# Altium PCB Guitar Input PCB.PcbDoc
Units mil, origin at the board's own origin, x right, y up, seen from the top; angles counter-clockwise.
Board outline 1700 x 1000 mil, 2 copper layers (Top Layer, Bottom Layer); 18 components, 10 nets, 47 pads, 16 vias.
Unrouted connection lines stored in the file: 9.
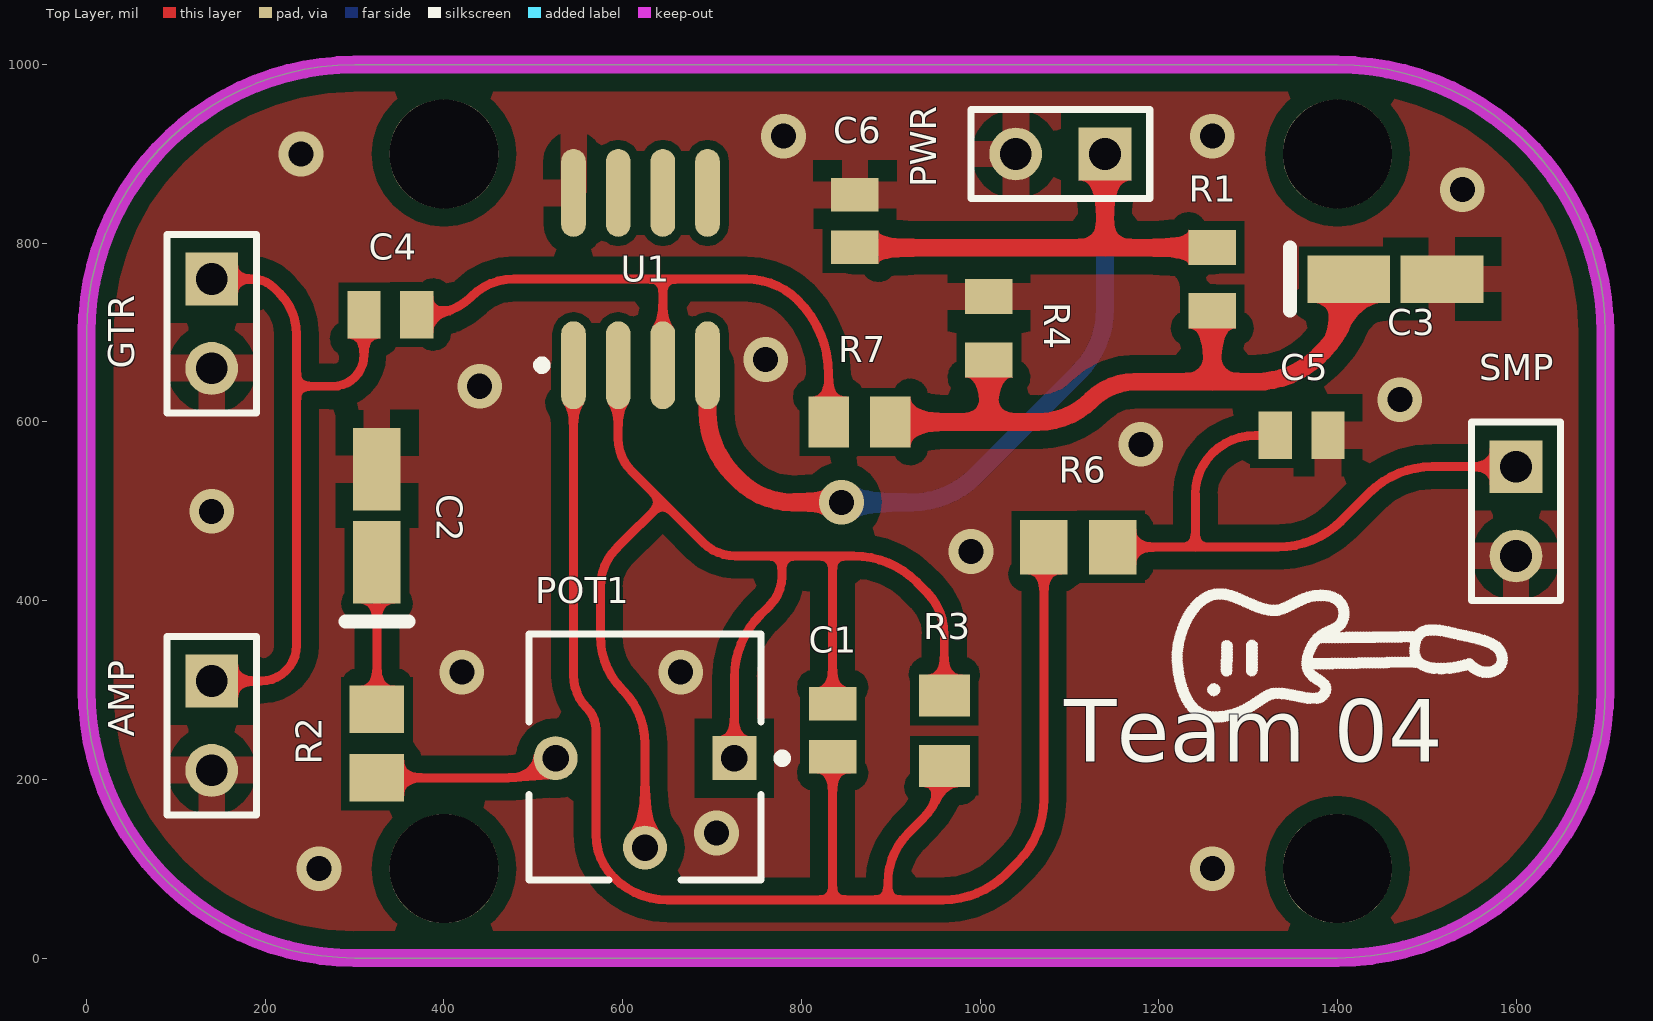
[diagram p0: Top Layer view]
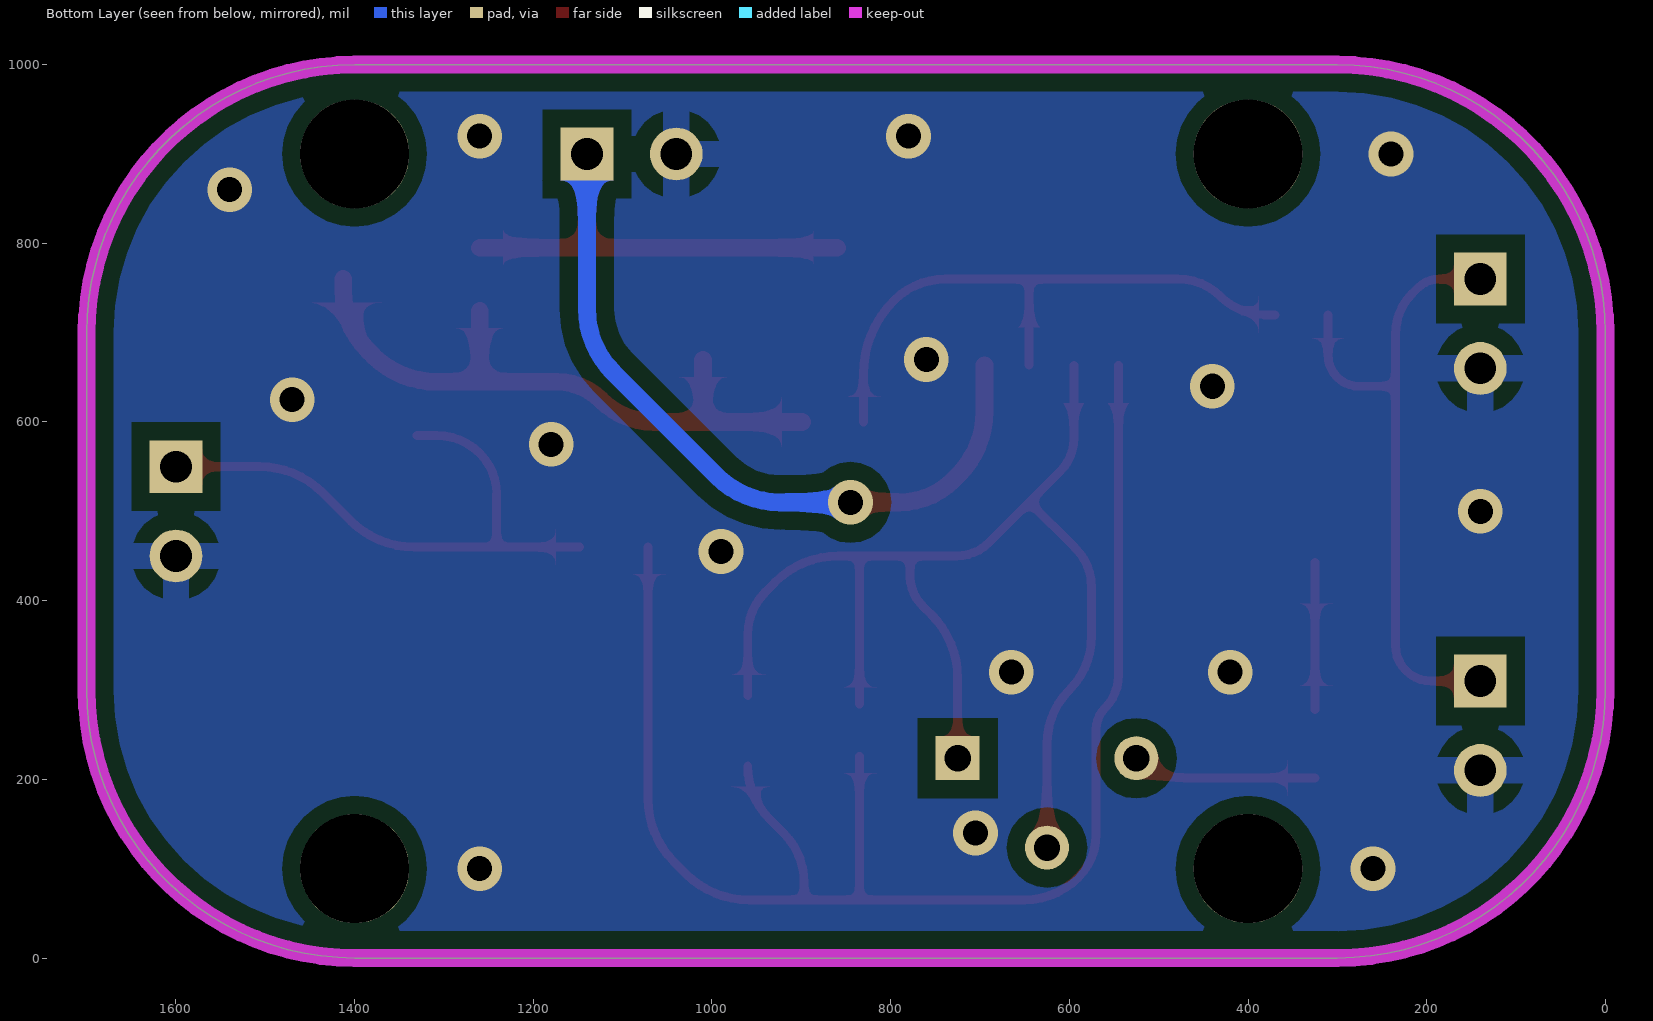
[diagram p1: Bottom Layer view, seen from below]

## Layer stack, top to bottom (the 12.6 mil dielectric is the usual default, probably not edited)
Top Solder: solder mask 0.4, Solder Resist, Dk 3.5
Top Layer: signal copper 1.4
Dielectric 1: dielectric 12.6, FR-4, Dk 4.8
Bottom Layer: signal copper 1.4
Bottom Solder: solder mask 0.4, Solder Resist, Dk 3.5

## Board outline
0,300 0,700 cw(c300,700) 300,1000 1400,1000 cw(c1400,700) 1700,700 1700,300 cw(c1400,300) 1400,0 300,0 cw(c300,300)

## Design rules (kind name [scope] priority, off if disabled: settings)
Clearance [All] p1: gap=10 ignorepadtopadclearanceinfootprint=FALSE except(0: Arc-Hole Track-Hole SMDPad-Hole THPad-Hole Via-Hole Fill-Hole Poly-Hole Region-Hole Text-Hole; 20: Arc-Fill Arc-Poly Arc-Region Track-Fill Track-Poly Track-Region THPad-Fill THPad-Poly THPad-Region Via-Fill Via-Poly Via-Region Fill-Fill Fill-Poly Fill-Region Poly-Poly Poly-Region Region-Region)
PolygonConnect [All] p1: thpad.connectstyle=Relief thpad.reliefconductorwidth=30 thpad.reliefentries=4 thpad.polygonreliefangle="90 Angle" thpad.airgapwidth=20 smdpad.connectstyle=Relief smdpad.reliefconductorwidth=30 smdpad.reliefentries=4 smdpad.polygonreliefangle="90 Angle" smdpad.airgapwidth=20 via.connectstyle=Direct via.reliefconductorwidth=30 via.reliefentries=4 via.polygonreliefangle="90 Angle" via.airgapwidth=20
RoutingVias [All] p1: holewidth=28 width=50 viastyle="Through Hole" minholewidth=28 minwidth=50 maxholewidth=28 maxwidth=50
SolderMaskExpansion [All] p1: expansion=4 istentingtop=FALSE
Width Width_1 [InNet('+2V5') OR InNet('+5V')] p1: maxlimit=30 minlimit=20 preferedwidth=25 minimp=50.000000 maximp=50.000000 favimp=50.000000
Width [All] p2: maxlimit=25 minlimit=10 preferedwidth=20 minimp=50.000000 maximp=50.000000 favimp=50.000000
30 further rules are at their usual default settings.

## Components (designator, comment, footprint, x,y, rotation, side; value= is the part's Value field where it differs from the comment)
AMP "AMPLIFIER_INPUT" HDR1X2 140,310 r270 top
C1 "270pF" FP-C0805C-DN-MFG 835,255 r270 top value="270 pF"
C2 "10uF" KEMT-A-3216-18-2_M 325,495 r90 top
C3 "10uF" KEMT-A-3216-18-2_M 1465,760 r0 top
C4 "100nF" FP-C0805C-DN-MFG 340,720 r0 top value="0.10 μF"
C5 "270pF" FP-C0805C-DN-MFG 1360,585 r180 top value="270 pF"
C6 "100 nF" FP-C0805C-DN-MFG 860,825 r90 top value="0.10 μF"
GTR "GUITAR_OUTPUT" HDR1X2 140,760 r270 top
POT1 "100K" BOUR-3362P 625,225 r180 top
PWR "POWER" HDR1X2 1140,900 r180 top
R1 "10K" RESC2013X60X35NL10T20 1260,760 r90 top
R2 "470" RESC2013X70X40ML20T20 325,240 r270 top
R3 "100K" RESC2013X60X35ML10T20 960,254.37 r270 top
R4 "10K" RESC2013X60X35NL10T20 1010,705 r270 top
R6 "470" RESC2013X70X40ML20T20 1110,460 r0 top
R7 "1M" RESC2013X70X40NL20T20 865,600 r180 top
SMP "SAMPLED_SIGNAL" HDR1X2 1600,550 r270 top
U1 "MCP6002" SOIC-SN8_M 620,760 r90 top

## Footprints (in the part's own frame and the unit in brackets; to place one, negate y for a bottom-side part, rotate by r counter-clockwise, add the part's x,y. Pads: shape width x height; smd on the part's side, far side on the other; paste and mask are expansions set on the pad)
BOUR-3362P [mm] "THD, 3-Leads, Body 6.6x6.99mm, Pitch 2.54mm"
  rect 1.25x1.25 hole 0.75: 1(-2.54,0.035)
  round 1.25 hole 0.75: 2(0,2.575) 3(2.54,0.035)
  silkscreen extent -4.03,-3.49 3.3,3.5, body extent -3.3,-3.49 3.3,3.49, height 4.95
FP-C0805C-DN-MFG [mm]
  rect 0.95x1.35 smd paste+0 mask+0: 1(-0.75,0) 2(0.75,0)
  body extent -1.4,-0.85 1.4,0.85, height 0.25
HDR1X2 [mm] "Connector; Header; 2 Position"
  rect 1.5x1.5 hole 0.9: 1(0,0)
  round 1.5 hole 0.9: 2(2.54,0)
  silkscreen extent -1.27,-1.27 3.81,1.27
KEMT-A-3216-18-2_M [mm] "Molded TAN Capacitor, 2-Leads, Body 3.4x1.8mm, IPC Low Density"
  rect 2.35x1.35 smd: 1(-1.325,0) 2(1.325,0)
  silkscreen extent -3,-0.9 -3,0.9, body extent -1.7,-0.9 1.7,0.9, height 1.8
RESC2013X60X35ML10T20 [mm] "Chip Resistor, 2-Leads, Body 2.1x1.35mm, IPC Low Density"
  rect 1.2x1.45 smd: 1(-1,0) 2(1,0)
  body extent -1.05,-0.68 1.05,0.67, height 0.6
RESC2013X60X35NL10T20 [mm] "Chip Resistor, 2-Leads, Body 2.1x1.35mm, IPC Medium Density"
  rect 1x1.35 smd: 1(-0.9,0) 2(0.9,0)
  body extent -1.05,-0.68 1.05,0.67, height 0.6
RESC2013X70X40ML20T20 [mm] "Chip Resistor, 2-Leads, Body 2.00x1.25mm, IPC Low Density"
  rect 1.35x1.55 smd: 1(-0.975,0) 2(0.975,0)
  body extent -1.1,-0.72 1.1,0.72, height 0.7
RESC2013X70X40NL20T20 [mm] "Chip Resistor, 2-Leads, Body 2.2x1.35mm, IPC Medium Density"
  rect 1.15x1.45 smd: 1(-0.875,0) 2(0.875,0)
  body extent -1.1,-0.72 1.1,0.72, height 0.7
SOIC-SN8_M [mm] "SOIC, 8-Leads, Body 4.9x3.9mm, Pitch 1.27mm, IPC Low Density"
  oval 2.5x0.7 smd: 1(-2.45,1.905) 2(-2.45,0.635) 3(-2.45,-0.635) 4(-2.45,-1.905) 5(2.45,-1.905) 6(2.45,-0.635) 7(2.45,0.635) 8(2.45,1.905)
  silkscreen extent -2.57,2.68 -2.33,2.93, body extent -2,-2.5 2,2.5, height 1.75

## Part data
AMP GTR PWR SMP: library part "Header 2", "Header, 2-Pin"
C1 C5: library part CMP-1036-02406-3, "CAP CER 270PF 50V C0G/NP0 0805", Capacitance="270 pF", Manufacturer=KEMET, Manufacturer Part Number=C0805C271J5GACTU, Package=C0805C-DN, Temperature="-55°C to +125°C", Temperature Characteristic=C0G, Temperature Coefficient=30ppm/°C, Temperature Range High=+125°C, Temperature Range Low=-55°C, Tolerance=0.05, Voltage Rating="50 V"
C2 C3: library part CMP-2000-05172-1, "Capacitor, Tantalum, 10 uF, +/- 10%, 10 V, -55 to 125 degC, 2-Pin SMD (1206), RoHS, Tape and Reel", Capacitance=10µF, ESR (Equivalent Series Resistance)=3.8Ohm, Lifetime @ Temp.=2000Hrs@85degC, Manufacturer=Kemet, Manufacturer Size Code=A, Operating Temperature=-55degC~125degC, Package / Case=1206(3216Metric), Package Description="2-Pin Surface Mount Device, Body 3.2 x 1.6 mm", Package Reference=1206, Standard Package=2,000, Tolerance=±10%, Voltage - Rated=10V
C4 C6: library part CMP-2007-00279-2, "CAP CER 0.1UF 50V X7R 0805", Capacitance="0.10 μF", Manufacturer=KEMET, Manufacturer Part Number=C0805C104K5RACTU, Package=C0805C-DN, Temperature="-55°C to +125°C", Temperature Characteristic=X7R, Temperature Coefficient=30ppm/°C, Temperature Range High=+125°C, Temperature Range Low=-55°C, Tolerance=0.1, Voltage Rating="50 V"
POT1: library part CMP-1747-00003-1, "Square Trimpot(R) Trimming Potentiometer, 100 KOhm, 300 V, -55 to 125 degC, 3-Pin THD, RoHS, Tube", Case\Package=Axial, Max Operating Temperature="155 degC", Min Operating Temperature="-55 degC", Package Quantity=200, Power Rating="250 mW", Resistance="1 mohm", Tolerance=1%, Voltage Rating="250 V"
R1 R4: library part CMP-1659-00013-4, "Chip Resistor, 10 KOhm, +/- 1%, 0.125 W, -55 to 155 degC, 0805 (2012 Metric), RoHS, Tape and Reel", Manufacturer=Yageo, Max Operating Temperature="155 degC", Min Operating Temperature="-55 degC", Package Quantity=5000, Voltage Rating="150 V"
R2 R6: library part CMP-2001-00549-5, "Chip Resistor, 470 Ohm, +/- 1%, 0.125 W, -55 to 155 degC, 0805 (2012 Metric), RoHS, Tape and Reel", Manufacturer=Panasonic, Max Operating Temperature="155 degC", Min Operating Temperature="-55 degC", Package Quantity=1, Voltage Rating="150 V"
R3: library part CMP-2100-03668-1, "Chip Resistor, 100 KOhm, +/- 1%, 0.125 W, -55 to 155 degC, 0805 (2012 Metric), RoHS, Tape and Reel", Case Code (Imperial)=0805, Case Code (Metric)=2012, Manufacturer=Yageo, Max Operating Temperature=155degC, Max Power Dissipation=125mW, Min Operating Temperature=-55degC, Package Description="2-Pin Surface Mounted Device, Body 2 x 1.25 mm", Package Quantity=1, Resistance=100KOhm, Temperature Coefficient=100ppm/degreesC, Tolerance=1%, Voltage Rating=150V
R7: library part CMP-2001-04378-5, "Chip Resistor, 1000 KOhm, +/- 1%, 0.125 W, -55 to 155 degC, 0805 (2012 Metric), RoHS, Tape and Reel", Manufacturer=Panasonic, Max Operating Temperature="155 degC", Min Operating Temperature="-55 degC", Package Quantity=5000, Voltage Rating="150 V"
U1: library part CMP-0187-00365-2, "1 MHz, Low-Power Operational Amplifier, 8-Pin SOIC, Industrial Temperature"

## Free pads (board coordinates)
  round 122.05 hole 122.05: MNT(400,100) MNT(400,900) MNT(1400,100) MNT(1400,900)

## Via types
v1: diameter 50, hole 28, Top Layer to Bottom Layer, tented both sides, 16 vias

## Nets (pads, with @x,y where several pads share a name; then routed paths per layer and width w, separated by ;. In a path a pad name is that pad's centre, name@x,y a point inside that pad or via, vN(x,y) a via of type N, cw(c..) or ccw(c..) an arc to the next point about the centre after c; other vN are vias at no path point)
+2V5: C3.1 R1.1 R4.2 R7.1 | length 744.3
  Top Layer w20: R7.1 1010,600 ; R4.2 1010,600 ; R1.1 1260,645 ; C3.1 1412.83,747.2 cw(c1317.8,747.2) 1385,680 1379.29,674.29 cw(c1308.58,745) 1308.58,645 1260,645 ; 1010,600 1064.64,600 ccw(c1064.64,685.36) 1125,625 cw(c1173.28,576.72) 1173.28,645 1260,645
+5V: C6.1 PWR.1 R1.2 U1.4 | length 1339.3
  Top Layer w20: U1.4 695,611.42 ccw(c795,611.42) 724.29,540.71 730,535 ccw(c790.36,595.36) 790.36,510 v1(845,510) ; C6.1@860,795 1140,795 ; PWR.1 1140,795 ; R1.2@1260,795 1140,795
  Bottom Layer w20: v1(845,510) 923.58,510 ccw(c923.58,610) 994.29,539.29 1110.71,655.71 ccw(c1040,726.42) 1140,726.42 PWR.1
GND: AMP.2 C2.2 C3.2 C5.1 C6.2 GTR.2 PWR.2 R4.1 SMP.2 U1.8
  other v1: 260,100 1260,100 705,140 420,320 665,320 990,455 140,500 1180,575 1470,625 440,640 760,670 1540,860 240,900 780,920 1260,920
NetAMP_1: AMP.1 C4.1 GTR.1 | length 738.5
  Top Layer w10: AMP.1 195,310 ccw(c195,350) 223.24,321.67 ccw(c195,350) 235,350 235,640 ; GTR.1 185.86,760 cw(c185.86,725.86) 210,750 215.86,744.14 cw(c169.64,697.93) 235,697.93 235,640 ; C4.1 310.47,675.28 cw(c274.72,675.28) 300,650 cw(c275.86,674.14) 275.86,640 235,640
NetC1_1: C1.1 POT1.1 POT1.2 R3.1 U1.2 | length 1457.4
  Top Layer w10: U1.2 595,581.42 ccw(c646.72,581.42) 610.15,544.85 644.64,510.36 ; POT1.2 625,239.64 ccw(c539.64,239.64) 600,300 cw(c660.36,360.36) 575,360.36 575,414.64 cw(c637.93,414.64) 593.43,459.14 644.64,510.36 ; POT1.1 725,313.58 cw(c825,313.58) 754.29,384.29 765,395 ccw(c733.11,426.89) 778.21,426.89 778.21,450 ; C1.1 835,450 ; R3.1 960,361.72 ccw(c891.72,361.72) 940,410 929.29,420.71 ccw(c858.58,350) 858.58,450 835,450 ; 644.64,510.36 655,500 689.85,465.15 ccw(c726.42,501.72) 726.42,450 778.21,450 ; 778.21,450 835,450
NetC1_2: C1.2 R3.2 R6.1 U1.1 | length 1747.9
  Top Layer w10: U1.1 545,316.21 ccw(c596.21,316.21) 560,280 cw(c535.86,255.86) 570,255.86 570,138.28 ccw(c638.28,138.28) 590,90 ccw(c650.36,150.36) 650.36,65 835,65 ; C1.2 835,65 ; R3.2 cw(c875.5,215) 935.25,155.25 920,140 ccw(c976.04,83.96) 896.79,83.96 896.79,65 ; R6.1 1071.61,178.04 cw(c971.61,178.04) 1042.32,107.32 1029.29,94.29 cw(c958.58,165) 958.58,65 896.79,65 ; 835,65 896.79,65
NetC2_1: C2.1 R2.1 | length 164.4
  Top Layer w10: R2.1 C2.1
NetC4_2: C4.2 R7.2 U1.3 | length 685.5
  Top Layer w10: C4.2 381.72,720 ccw(c381.72,788.28) 430,740 cw(c478.28,691.72) 478.28,760 645,760 ; U1.3 645,760 ; R7.2 830.55,653.25 830.55,653.31 ccw(c713.46,653.31) 796.21,736.16 ccw(c738.58,678.43) 738.58,760 645,760
NetC5_2: C5.2 R6.2 SMP.1 | length 666.2
  Top Layer w10: R6.2 1240.98,460 ; C5.2 1308.28,585 ccw(c1308.28,516.72) 1260,565 ccw(c1305.91,519.09) 1240.98,519.09 1240.98,460 ; SMP.1 1506.42,550 ccw(c1506.42,450) 1435.71,520.71 1404.29,489.29 cw(c1333.58,560) 1333.58,460 1240.98,460
NetPOT1_3: POT1.3 R2.2 | length 205.9
  Top Layer w10: R2.2 471.87,201.61 ccw(c471.87,276.75) POT1.3
pads on no net: U1.5 U1.6 U1.7

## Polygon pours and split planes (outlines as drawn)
GND on Top Layer "GND_L01_P000" (solid, pour order 0): 0,300 0,700 cw(c300,700) 300,1000 1400,1000 cw(c1400,700) 1700,700 1700,300 cw(c1400,300) 1400,0 300,0 cw(c300,300)
GND on Bottom Layer "GND_L02_P001" (solid, pour order 1): 0,300 0,700 cw(c300,700) 300,1000 1400,1000 cw(c1400,700) 1700,700 1700,300 cw(c1400,300) 1400,0 300,0 cw(c300,300)

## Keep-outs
Keep-Out Layer:
  the board outline again, w20

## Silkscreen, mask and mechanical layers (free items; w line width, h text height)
Top Overlay:
  drawing of 4 lines, arcs and shapes, not listed
  text "Team 04" at 1094.19,196.73 h120
Mechanical 1:
  the board outline again, w10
